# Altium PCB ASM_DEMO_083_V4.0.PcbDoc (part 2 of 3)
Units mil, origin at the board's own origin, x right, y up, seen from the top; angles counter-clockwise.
Board outline 4534.65 x 3225.59 mil, 2 copper layers (Top Layer, Bottom Layer); 192 components, 109 nets, 496 pads, 1295 vias.
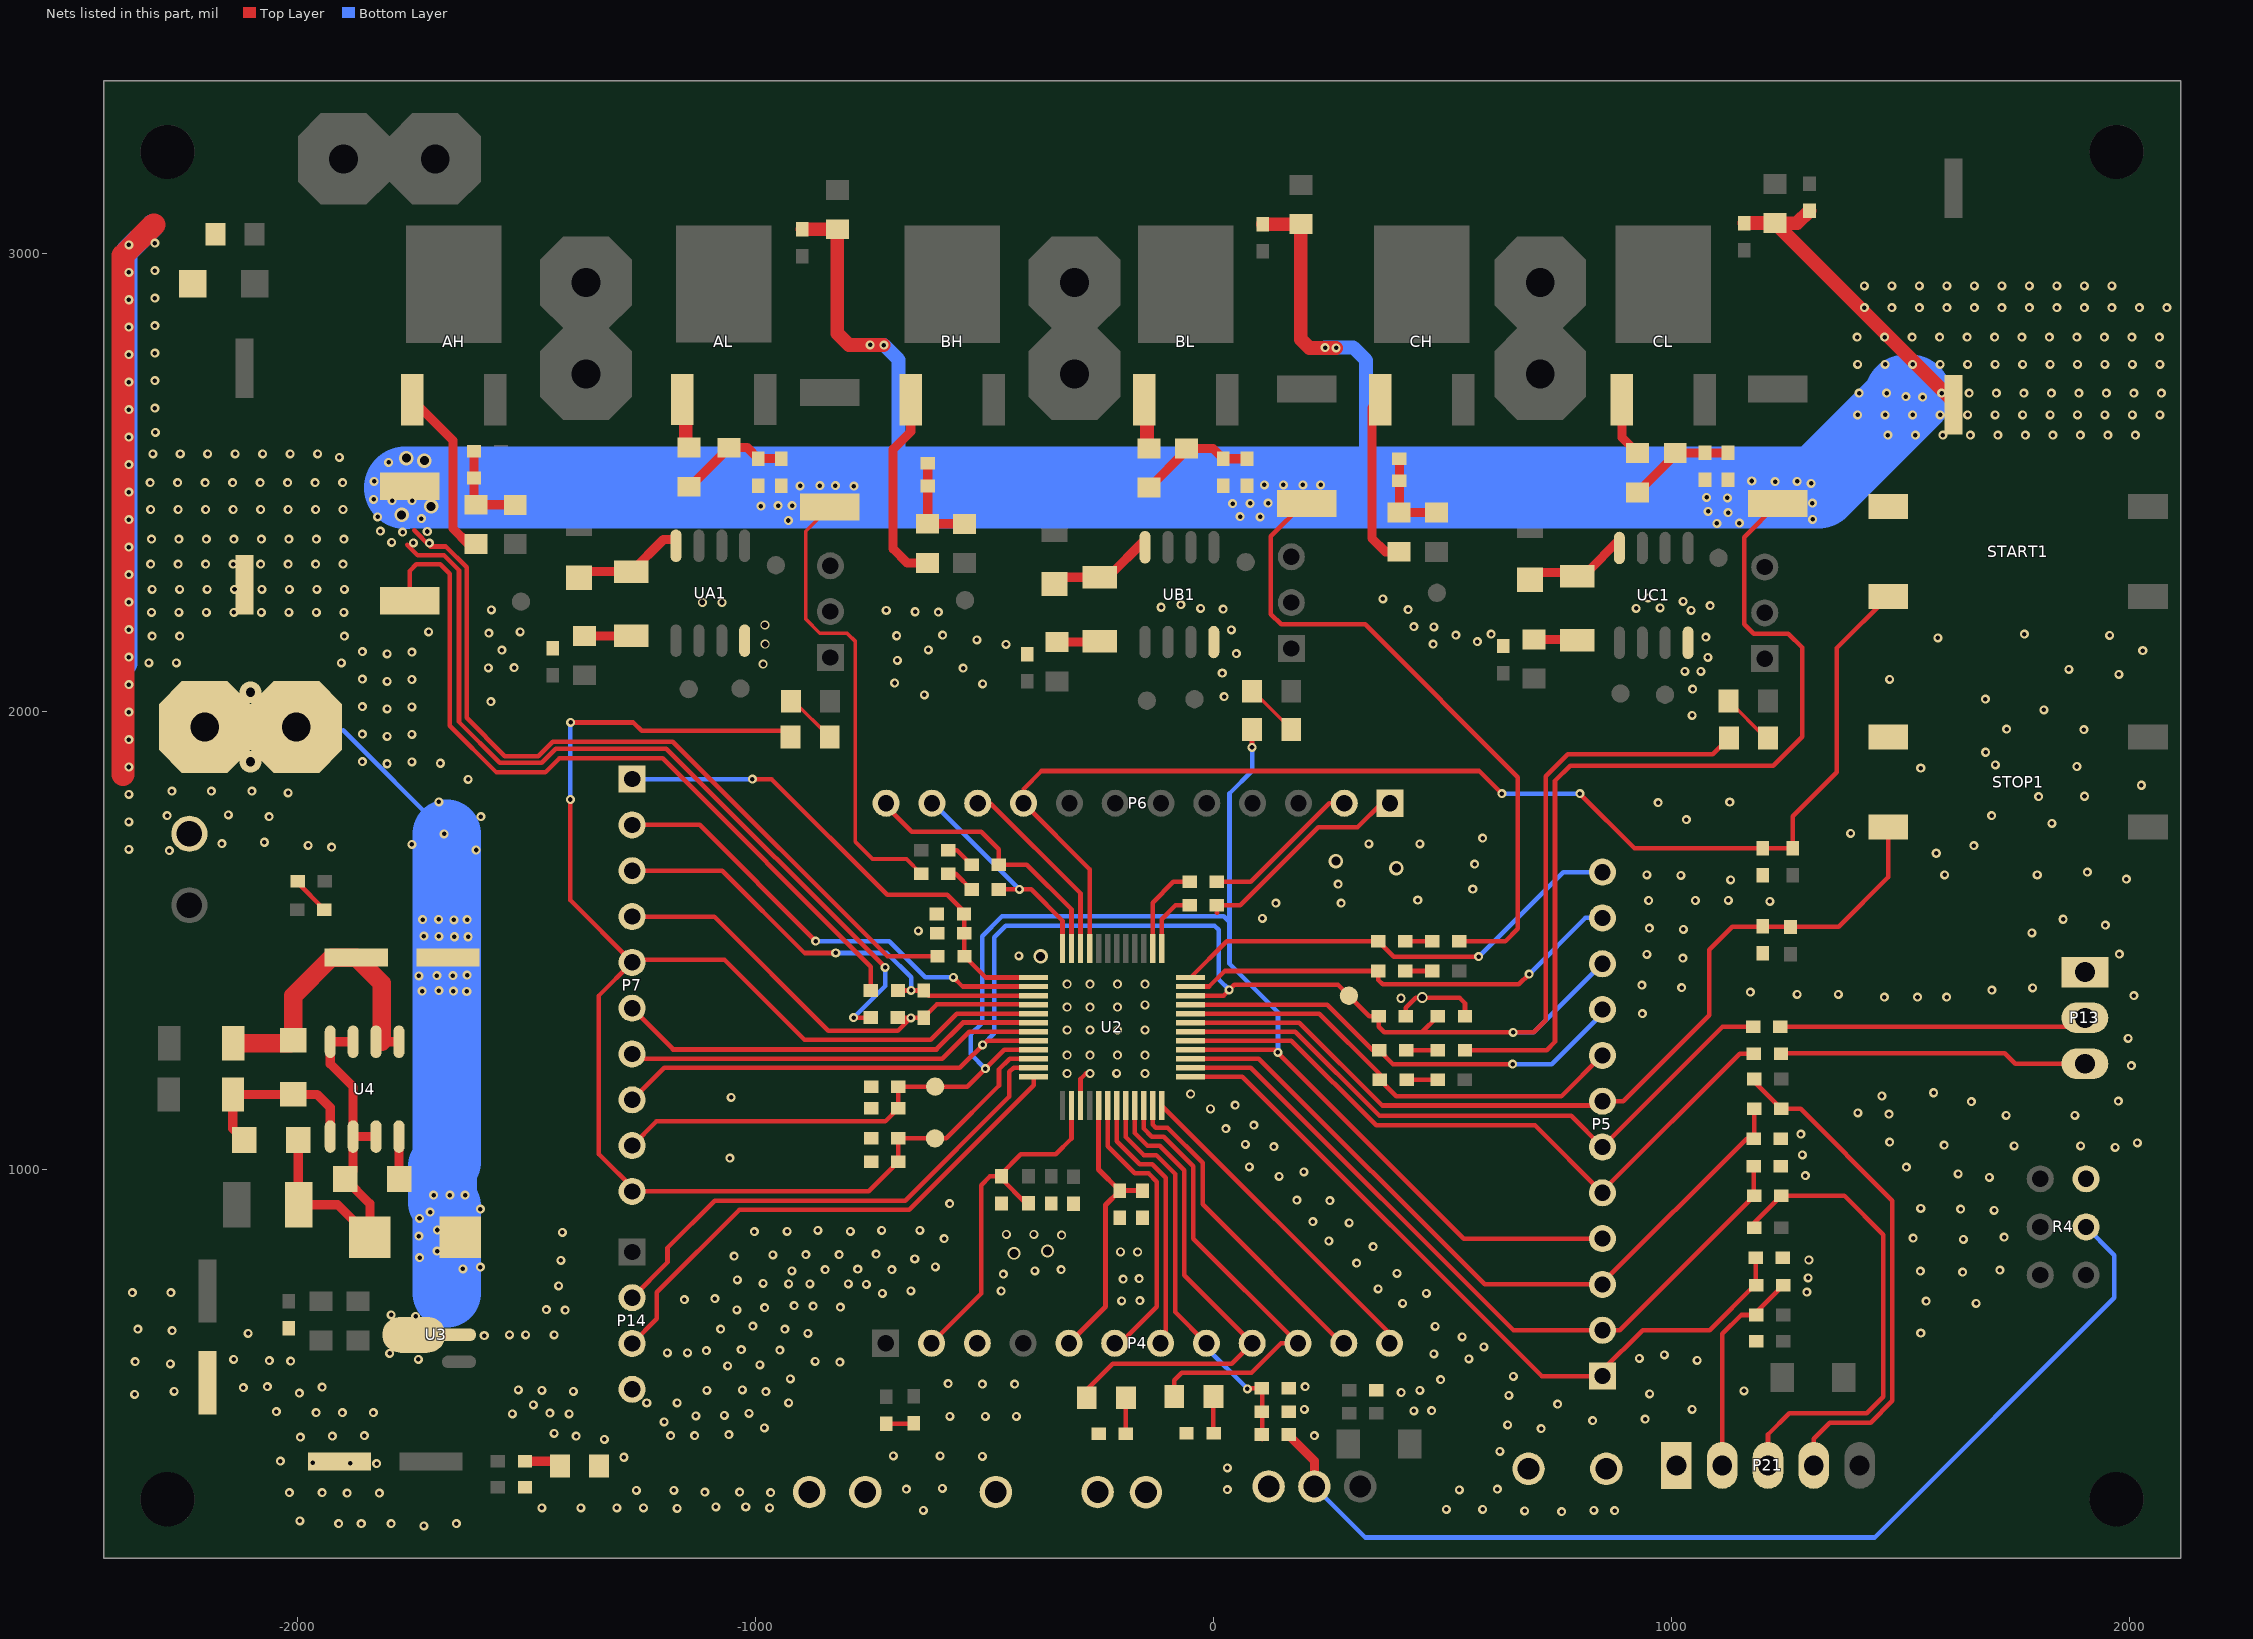
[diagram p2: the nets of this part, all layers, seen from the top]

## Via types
v1: diameter 19.68, hole 9.84, Top Layer to Bottom Layer, 1240 vias
v2: diameter 19.68, hole 11.81, Top Layer to Bottom Layer, 33 vias
v3: diameter 47.24, hole 20, Top Layer to Bottom Layer, 10 vias
v4: diameter 31.5, hole 19.68, Top Layer to Bottom Layer, 7 vias
v5: diameter 27.56, hole 19.68, Top Layer to Bottom Layer, 2 vias
v6: diameter 19.68, hole 13.78, Top Layer to Bottom Layer, 2 vias
v7: diameter 23.62, hole 15.75, Top Layer to Bottom Layer, 1 vias

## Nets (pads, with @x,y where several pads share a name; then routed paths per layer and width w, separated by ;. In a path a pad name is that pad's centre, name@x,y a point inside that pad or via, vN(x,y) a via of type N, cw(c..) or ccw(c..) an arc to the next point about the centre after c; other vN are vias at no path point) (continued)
GND: AGND.1 C1.2 C2.1 C3.2 C6.1 C12.2 C15.1 C17.1 C19.1 C21.2 C23.1 C25.1 C26.1 C27.1 C28.2 C31.2 C32.2 C33.2 C36.2 C37.1 C43.1 C44.1 C45.1 C561.2 C581.2 C601.2 CA-5.1 CC3.2 CF1.2 D02.1 DM_IN.2 G1.1 G2.1 G3.1 G4.1 G5.1 G12.1 G13.1 G14.1 LED.2 P4.3 P13.1 P14.4 P21.1 R4.2 R10.2 R14.2 R20.1 R43.1 R56.2 R58.2 R60.2 R69.2 R76.1 RA-5.2 RT-1.1 START1.1 STOP1.1 U2.3 U3.2 UA1.4 UB1.4 UC1.4 | length 5585.3
  Top Layer w10: R69.2@-1754.72,2242.13 -1754.72,2307.09 -1740.16,2321.65 -1687.8,2321.65 -1666.93,2300.79 -1666.93,1969.29 -1564.96,1867.32 -1458.27,1867.32 -1427.56,1898.03 -1202.36,1898.03 -747.64,1443.31 RT-1.1@-747.64,1391.34 ; R76.1@-714.57,445.89 C44.1@-653.94,445.89 ; U2.3@-290.06,1140.14 -290.06,1198.13 -278.05,1210.14 v2(-269.43,1210.14) ; R60.2@420.08,1335.51 420.08,1354.02 441.73,1375.67 537.32,1375.67 549.21,1363.78 C601.2@549.21,1335.04
  Top Layer w50: -2380.31,1862.6 -2380.31,2995.67 -2312.99,3062.99
  Bottom Layer w10: -1899.61,1959.06 v1@-1673.62,1733.07
  Bottom Layer w50: -2373.23,2105.12 -2373.23,3002.76 -2314.96,3061.02
  Bottom Layer w150: -1673.62,731.1 -1673.62,920.2 -1682.64,929.22 -1682.64,1007.79 -1673.62,1016.8 v1@-1673.62,1733.07
  other v1: -1723.62,222.83 -1909.84,227.56 -1860.24,227.56 -1794.88,227.56 -1652.36,227.56 -1994.09,233.46 760.24,253.54 679.13,255.12 -633.07,256.3 830.32,256.3 875.98,255.91 508.66,258.66 587.8,258.66 -1170.47,260.63 -1466.14,261.81 -1380.71,261.81 -1302.36,261.81 -1244.09,261.81 -968.9,261.81 -1086.22,264.17 -1020.87,264.17 -1890.94,294.09 -1820.87,294.09 -2016.93,295.28 -1945.67,295.28 -966.54,295.28 -1110.24,296.46 -1034.25,296.46 -1259.45,300 -1177.56,300 537.01,301.18 30.71,301.97 -670.08,302.76 619.69,302.76 -591.73,304.72 30.71,349.21 -1826.77,358.27 -1883.86,359.45 -1965.75,360.63 -2037.01,364.17 -1287.01,372.44 -504.33,374.41 -698.82,375.2 -596.46,375.2 625.2,385.04 -1329.53,411.42 -1992.91,416.14 -1923.23,418.5 -1391.34,418.5 -1853.15,419.68 -1184.65,419.68 -1132.68,419.68 220.47,419.68 -1057.87,422.05 -1438.98,424.41 715.35,435.04 -980.31,436.61 642.52,443.31 -1199.21,449.61 827.95,452.36 942.52,455.51 -575.2,461.42 -497.64,461.42 -429.92,461.42 -1129.92,462.99 -1067.72,463.78 -1530.31,467.32 -1406.69,467.32 -1448.43,468.5 -1013.78,468.11 -1958.66,469.68 -1901.57,469.68 -1833.86,469.68 -2045.28,472.05 437.4,473.62 476.38,474.02 198.82,477.17 1045.28,476.77 -1484.65,486.61 751.18,488.19 -1237.01,490.94 -1170.47,490.94 -927.17,490.94 644.88,507.48 -2355.12,509.84 952.36,511.02 -1995.28,512.6 409.84,513.78 -2268.5,516.14 -1397.24,516.14 -977.17,515.75 1158.27,517.32 -1466.14,518.5 -1105.51,518.5 450.79,518.5 -1517.32,519.68 -1028.35,519.68 -2117.72,524.41 -1945.67,525.59 -2065.35,526.77 200.39,526.77 -504.33,532.28 -433.86,532.28 -579.13,533.07 496.06,542.13 -923.23,543.31 654.72,548.82 -1060.24,571.65 -990.16,574.02 -2276.77,576.38 -815.35,579.92 -2353.94,581.1 -2014.57,582.28 -869.29,581.89 -2060.63,583.46 1055.91,583.86 -2138.98,585.83 -1735.43,585.83 557.48,587.4 929.92,588.19 984.25,596.06 481.1,598.03 -1798.43,599.21 -1191.73,600.39 -1148.03,600.39 -1106.69,605.12 -946.46,606.3 -1030.71,607.48 590.55,613.39 542.91,635.43 -1591.73,638.19 -1536.61,639.76 -1501.18,639.76 -1438.98,639.76 -2107.09,642.91 -885.43,642.91 1544.09,643.31 -2273.23,648.82 -2348.03,652.36 -1075.59,652.36 -935.43,652.36 483.86,658.27 -1005.51,658.66 -1741.34,679.92 -1794.88,683.46 -1455.91,694.49 -1414.96,693.7 -1040.16,694.09 -979.53,698.82 -814.57,700 -874.02,702.36 -915.35,703.54 412.99,708.27 1664.96,708.27 1555.91,712.99 -200.39,713.78 -160.63,714.57 -1154.72,716.54 -1088.19,718.5 -722.44,729.92 464.96,730.31 -2359.84,731.89 -2275.59,731.89 1295.67,732.68 -463.39,735.35 -660.63,735.83 359.45,739.76 -1429.53,746.46 -757.48,749.61 -927.17,750.79 -881.1,750.79 -796.85,750.79 -983.07,751.97 -1038.98,759.45 -197.24,761.42 -162.2,762.2 1298.03,763.78 -458.66,772.36 400.79,774.02 1635.43,776.77 -920.08,779.53 -389.76,779.45 1543.31,778.74 1716.93,780.71 -847.64,781.89 -701.97,781.89 -332.68,781.81 -1638.19,783.46 -776.38,783.07 -1600.39,787.4 -607.09,787.8 312.6,796.06 -1424.41,801.97 -651.97,805.51 -1732.68,808.27 -1046.46,811.42 -961.81,814.17 -889.76,814.96 -816.93,814.96 -736.22,815.75 -1694.49,822.44 348.43,832.28 251.97,844.49 1637.4,848.03 -587.8,849.61 1527.56,850.79 1725.98,852.76 -1734.25,855.12 -1421.26,863.39 -1001.97,864.96 -930.71,865.75 -792.52,865.75 -1694.09,868.5 -863.39,867.72 -724.41,867.72 -640.55,867.72 296.46,884.25 216.93,886.61 -1733.07,893.7 -1709.84,907.48 1704.33,911.42 -1600,914.17 1631.1,914.17 1544.09,915.75 -575.98,925.98 254.33,932.68 182.28,933.86 -1702.36,944.49 -1666.54,944.49 -1633.46,944.49 1694.09,983.46 143.31,985.43 1292.13,987.4 1625.59,990.94 197.64,995.28 1512.99,1005.51 78.74,1006.3 -1055.51,1025.59 1285.83,1032.28 1968.5,1048.82 131.89,1050.39 1748.03,1051.97 1893.31,1051.97 1595.28,1053.94 69.69,1055.51 2016.93,1058.66 1476.38,1060.24 1282.28,1077.56 27.17,1089.76 88.19,1097.24 1730.71,1118.9 1880.71,1118.9 1474.8,1121.65 1407.09,1124.41 47.64,1141.34 1654.72,1148.82 1975.59,1150 -1052.76,1157.87 1459.06,1161.02 1572.44,1168.11 -211.42,1210.63 2003.94,1227.56 1996.85,1287.01 936.22,1340.94 1464.57,1376.77 1537.01,1376.77 1600.79,1376.77 2009.45,1380.31 1274.41,1383.07 1364.17,1383.07 1172.05,1387.8 -1629.92,1389.37 -1727.56,1389.76 -1659.06,1390.16 -1690.94,1390.94 1699.61,1392.13 1022.05,1397.64 1788.19,1396.85 935.43,1403.15 -1734.65,1423.23 -1695.28,1424.02 -1660.24,1424.02 -1629.13,1424.8 1024.8,1461.81 -424.8,1466.93 946.46,1470.08 1977.56,1470.87 -1690.94,1509.45 -1657.09,1508.66 -1626.77,1508.66 -1723.62,1510.24 1786.61,1517.32 -644.09,1521.65 1025.98,1524.8 951.57,1527.56 1947.24,1533.86 -1726.38,1546.06 -1691.34,1546.46 -1658.27,1545.67 -1629.13,1546.06 1855.12,1546.85 107.09,1548.82 136.22,1582.28 278.74,1582.28 1214.96,1585.83 446.06,1588.58 950,1587.8 1052.36,1587.8 1124.02,1588.19 566.14,1612.6 272.44,1623.62 1129.13,1632.68 1992.91,1634.25 1020.47,1642.52 946.46,1643.7 1596.46,1643.7 1798.43,1643.7 1907.87,1649.61 570.47,1667.32 1577.95,1690.94 -2279.13,1696.85 -1609.45,1698.03 -2367.32,1699.21 -1924.8,1704.33 1660.24,1707.48 -1975.98,1708.27 -1749.61,1710.24 339.37,1711.42 450.79,1711.42 -2164.57,1712.2 -2071.65,1714.96 587.8,1724.02 -1679.53,1733.07 1390.94,1734.25 1830.32,1755.91 -2367.32,1759.21 1032.28,1764.17 -2061.42,1770.87 -1599.21,1770.87 -2283.86,1772.83 1698.82,1773.23 -2150.39,1774.8 970.87,1801.57 -1690.94,1803.15 1127.17,1802.76 1801.18,1814.57 1901.57,1815.35 -2367.32,1819.21 -2019.68,1822.83 -2273.62,1826.77 -2187.4,1826.77 -2099.21,1826.77 2025.98,1839.37 -1626.77,1852.36 1544.09,1876.77 -2367.32,1879.21 1885.04,1880.31 1707.09,1883.86 -1803.94,1886.3 -1687.4,1887.4 -1749.61,1890.24 -1857.87,1891.02 1685.83,1911.42 -2367.32,1939.21 -1803.94,1946.3 -1749.61,1950.24 -1857.87,1951.02 1900,1960.63 1731.5,1961.81 1045.28,1992.13 -2367.32,1999.21 1812.99,2003.94 -1803.94,2006.3 -1749.61,2010.24 -1857.87,2011.02 -1577.17,2022.05 1685.04,2027.56 23.23,2032.68 -630.71,2036.61 1046.06,2049.21 -2367.32,2059.21 -503.94,2060.63 -696.06,2062.6 -1803.94,2066.3 -1749.61,2070.24 1476.38,2070.47 -1857.87,2071.02 1976.77,2081.5 19.29,2084.25 1029.13,2087.8 1064.17,2087.8 1867.72,2092.52 -546.46,2094.88 -1582.68,2095.67 -1526.77,2096.06 -2323.62,2106.3 -2263.62,2106.3 -1903.62,2106.3 -689.76,2111.81 1079.53,2118.5 -2367.32,2119.21 -1803.94,2126.3 50.39,2126.77 -1749.61,2130.24 -1857.87,2131.02 2028.74,2133.46 -1553.15,2134.25 -622.44,2134.65 -452.76,2146.85 479.53,2147.24 575.98,2153.15 -516.54,2156.69 1581.5,2161.02 1074.8,2162.99 -2316.93,2164.96 -2256.93,2164.96 -1896.93,2164.96 -691.34,2165.75 1956.3,2166.54 -590.94,2167.32 529.53,2167.32 606.3,2169.29 1770.08,2169.29 -1581.5,2171.65 -1712.99,2174.02 -1513.39,2174.02 -2367.32,2179.21 38.98,2178.74 481.5,2185.04 437.4,2185.83 -2318.11,2216.93 -2258.11,2216.93 -2198.11,2216.93 -2138.11,2216.93 -2078.11,2216.93 -2018.11,2216.93 -1958.11,2216.93 -1898.11,2216.93 -600.39,2217.32 -651.18,2218.11 -714.17,2221.26 1042.91,2221.26 -1576.38,2222.05 21.26,2223.62 424.8,2222.83 -27.95,2225.59 922.83,2225.59 975.2,2226.38 -114.17,2227.95 1084.25,2231.5 -71.26,2233.46 -2367.32,2239.21 1025.59,2240.94 370.08,2246.06 949.21,2248.43 -2316.93,2266.93 -2256.93,2266.93 -2196.93,2266.93 -2136.93,2266.93 -2076.93,2266.93 -2016.93,2266.93 -1956.93,2266.93 -1896.93,2266.93 -2367.32,2299.21 -2320.08,2322.05 -2260.08,2322.05 -2200.08,2322.05 -2140.08,2322.05 -2080.08,2322.05 -2020.08,2322.05 -1960.08,2322.05 -1900.08,2322.05 -2367.32,2359.21 -2318.11,2376.77 -2258.11,2376.77 -2198.11,2376.77 -2138.11,2376.77 -2078.11,2376.77 -2018.11,2376.77 -1958.11,2376.77 -1898.11,2376.77 -2367.32,2419.21 -2320.08,2441.34 -2260.08,2441.34 -2200.08,2441.34 -2140.08,2441.34 -2080.08,2441.34 -2020.08,2441.34 -1960.08,2441.34 -1900.08,2441.34 -2367.32,2479.21 -2320.87,2500 -2260.87,2500 -2200.87,2500 -2140.87,2500 -2080.87,2500 -2020.87,2500 -1960.87,2500 -1900.87,2500 -2367.32,2539.21 -1907.87,2555.12 -2315.35,2562.6 -2255.35,2562.6 -2195.35,2562.6 -2135.35,2562.6 -2075.35,2562.6 -2015.35,2562.6 -1955.35,2562.6 -2367.32,2599.21 -2309.84,2609.45 -2367.32,2659.21 -2310.63,2662.68 -2367.32,2719.21 -2310.63,2722.68 -2367.32,2779.21 -2310.63,2782.68 -2367.32,2839.21 -2310.63,2842.68 -2367.32,2899.21 -2310.63,2902.68 -2367.32,2959.21 -2310.63,2962.68 -2367.32,3019.21 -2310.63,3022.68
  other v2: 1299.76,803.03 -165.35,820.47 -202.76,820.87 -331.1,857.48 -451.97,859.06 -392.13,859.06 -6.3,1133.07 -49.61,1165.35 -319.43,1210.14 -149.43,1210.14 -319.43,1250.14 -269.43,1250.14 -209.43,1250.14 -149.43,1250.14 -319.43,1305.14 -269.43,1305.14 -209.43,1305.14 -149.43,1305.14 -319.43,1355.14 -269.43,1355.14 -209.43,1355.14 -149.43,1360.14 409.45,1374.41 -319.43,1405.14 -269.43,1405.14 -209.43,1405.14 -149.43,1405.14 -983.07,2103.54 -1115.72,2238.68 -1072.72,2238.68
  other v3: -2101.97,1890.54 -2101.97,2042.54
  other v4: -377.17,1465.75 399.21,1658.27 267.32,1673.62
  other v5: -435.43,817.64 -362.2,822.76
  other v6: -978.35,2147.24 -979.13,2189.37
  other v7: 455.91,1375.98
HALL_A: C31.1 P5.3 R54.2 U2.15 | length 1632.3
  Top Layer w10: U2.15@-49.9,1242.5 99.23,1242.5 592.05,749.68 P5.3@849.21,749.68 849.21,753.26 1163.98,1068.03 C31.1@1179.76,1068.03 ; C31.1@1180.24,1068.5 R54.2@1180.24,1133.03
HALL_B: C32.1 P5.2 R57.2 U2.14 | length 1653.6
  Top Layer w10: U2.14@-49.9,1222.82 81.91,1222.82 655.04,649.68 P5.2@849.21,649.68 886.89,649.68 R57.2@1180.24,943.03 ; R57.2@1179.76,943.5 C32.1@1179.76,1008.03
HALL_C: C33.1 P5.1 R62.2 U2.13 | length 1652.4
  Top Layer w10: U2.13@-49.9,1203.13 63.01,1203.13 716.46,549.68 P5.1@849.21,549.68 849.21,562.05 936.85,649.68 1083.35,649.68 1183.46,749.8 C33.1@1183.46,808.03
LDO15: C27.2 C28.1 P4.5 U2.5 | length 633.7
  Top Layer w11: P4.5@-315.35,621.26 -235.43,701.18 -235.43,923.23 C27.2@-204.33,954.33 ; U2.5@-250.69,1140.14 -250.69,1000.69 C27.2@-204.33,954.33 ; C28.1@-154.72,954.33 C27.2@-204.33,954.33
LED2: L2.1 P4.9 U2.9 | length 1061.8
  Top Layer w10: L2.1@-276.61,502.34 -276.61,519.8 -219.68,576.73 40.12,576.73 P4.9@84.65,621.26 -63.62,769.53 -63.62,999.03 -116.71,1052.13 -143.86,1052.13 -171.95,1080.21 U2.9@-171.95,1140.14
LED3: L1.1 P4.10 U2.10 | length 1012.7
  Top Layer w10: U2.10@-152.26,1140.14 -152.26,1090.05 -134.33,1072.13 -108.43,1072.13 -43.62,1007.32 -43.62,849.53 P4.10@184.65,621.26 147.62,621.26 83.09,556.73 -69.29,556.73 -85.63,540.39 L1.1@-85.63,505.12
LKS_PIN10: P4.7 U2.7 | length 584.6
  Top Layer w10: U2.7@-211.32,1140.14 -211.32,1062.5 -160.94,1012.13 -133.28,1012.13 -103.62,982.47 -103.62,632.99 P4.7@-115.35,621.26
LKS_PIN11: P4.6 U2.6 | length 626.2
  Top Layer w10: U2.6@-231,1140.14 -231,1051.47 -171.65,992.13 -141.57,992.13 -123.62,974.18 -123.62,700.69 -203.06,621.26 P4.6@-215.35,621.26
NetAH_1: AH.1 K1.2 | length 382.5
  Top Layer w20: AH.1@-1749.21,2681.1 -1660.24,2592.13 -1660.24,2400 -1626.18,2365.94 K1.2@-1609.84,2365.94
NetAL_1: AL.1 K2.2 | length 112.7
  Top Layer w20: AL.1@-1164.57,2681.1 AL.1@-1151.97,2668.5
  Top Layer w30: AL.1@-1151.97,2668.5 -1151.97,2583.66 K2.2@-1144.88,2576.57
NetBH_1: BH.1 K3.2 | length 429.6
  Top Layer w20: BH.1@-660.63,2681.1 -660.63,2611.42 -699.21,2572.83 -699.21,2355.51 -668.31,2324.61 K3.2@-624.02,2324.61
NetBL_1: BL.1 K4.2 | length 67.8
  Top Layer w30: K4.2@-144.88,2573.97 BL.1@-144.88,2641.73
NetC7_1: C7.1 K1.1 K+A1.2 R21.2 | length 204.2
  Top Layer w20: C7.1@-1614.12,2510.11 R21.2@-1614.17,2568.11 ; C7.1@-1614.12,2510.11 -1614.12,2455.85 K1.1@-1609.84,2451.57 -1524.21,2451.57 K+A1.2@-1524.02,2451.38
NetC11_1: C11.1 K2.1 K-A1.1 R31.2 | length 246.9
  Top Layer w20: K2.1@-1144.88,2490.94 -1142.52,2490.94 K-A1.1@-1057.48,2575.98 ; K-A1.1@-1057.48,2576.77 -1017.61,2576.77 R31.2@-993.28,2552.44 -993.2,2552.36 C11.1@-943.31,2552.36
NetC16_1: C16.1 K3.1 K+B1.2 R39.2 | length 212.8
  Top Layer w20: R39.2@-623.62,2542.13 -623.62,2410.63 K3.1@-624.02,2410.24 -543.5,2410.24 K+B1.2@-543.31,2410.04
NetC20_1: C20.1 K4.1 K-B1.1 R45.2 | length 261.3
  Top Layer w20: K4.1@-140.45,2489.02 -58.66,2570.81 K-B1.1@-58.66,2574.8 -1.18,2574.8 R45.2@21.65,2551.97 73.28,2551.97 C20.1@73.44,2551.81
NetC24_1: C24.1 K5.1 K+C1.2 R50.2 | length 200
  Top Layer w20: R50.2@405.91,2551.97 405.91,2435.43 K5.1@405.12,2434.65 405.32,2434.45 K+C1.2@487.4,2434.45
NetC34_1: C34.1 K6.1 K-C1.1 R63.2 | length 232.8
  Top Layer w20: K6.1@926.18,2478.7 1012.5,2565.02 C34.1@1123.25,2565.02
NetCAH1_1: CAH1.1 D1.2 UA1.8 | length 240.8
  Top Layer w20: CAH1.1@-1385.04,2305.91 -1271.44,2305.91 D1.2@-1270.91,2305.37 -1200.38,2375.9 UA1.8@-1173.69,2375.9
NetCBH1_1: CBH1.1 D2.2 UB1.8 | length 230.6
  Top Layer w20: CBH1.1@-346.06,2293.31 -230.62,2293.31 UB1.8@-149.21,2374.72
NetCCH1_1: CCH1.1 D4.2 UC1.8 | length 225.3
  Top Layer w20: CCH1.1@690.55,2303.54 814.65,2303.54 UC1.8@886.22,2375.11
NetCF1_1: CF1.1 DD6.2 RP1.2 U4.5 U4.6 | length 659
  Top Layer w20: U4.6@-1827.95,1279.44 -1815.75,1279.44 U4.5@-1777.95,1279.44
  Top Layer w40: DD6.2@-2139.44,1275.84 -2015.5,1275.84 RP1.2@-2008.66,1282.68 -2008.66,1379.53 -1925.2,1462.99 CF1.1@-1871.26,1462.99 -1815.75,1407.48 -1815.75,1279.44
NetCF2_1: CF2.1 DP1.2 RP1.1 U4.1 | length 418.7
  Top Layer w20: DP1.2@-2140.23,1164.42 -2008.81,1164.42 RP1.1@-2008.66,1164.57 -1956.69,1164.57 -1927.95,1135.83 U4.1@-1927.95,1072.44 ; DP1.2@-2139.2,1182.28 -2140.62,1183.71 -2140.62,1089.83 CF2.1@-2115.75,1064.96
NetCF2_2: CF2.2 D02.2 PL1.2 RP2.2 U4.2 U4.3 U4.7 U4.8 | length 902.8
  Top Layer w20: CF2.2@-1997.64,1064.96 -1997.64,924.37 PL1.2@-1996.89,923.62 -1911.89,923.62 D02.2@-1841.41,853.15 -1841.41,926.06 RP2.2@-1895.28,979.92 -1877.95,997.24 U4.2@-1877.95,1072.44 ; U4.7@-1877.95,1279.44 U4.8@-1927.95,1279.44 -1927.95,1231.1 -1877.95,1181.1 U4.2@-1877.95,1072.44 ; U4.3@-1827.95,1072.44 U4.2@-1877.95,1072.44
NetCH_1: CH.1 K5.2 | length 381.2
  Top Layer w20: CH.1@364.17,2681.1 346.06,2662.99 346.06,2378.74 375.79,2349.02 K5.2@405.12,2349.02
NetCL_1: CL.1 K6.2 | length 131
  Top Layer w20: CL.1@891.73,2681.1 891.73,2598.78 K6.2@926.18,2564.33
NetD1_1: D1.1 R79.2 | length 102
  Top Layer w20: R79.2@-1372.83,2165.16 -1271.12,2165.16 D1.1@-1270.91,2165.37
NetD2_1: D2.1 R78.2 | length 94.2
  Top Layer w20: R78.2@-341.34,2151.77 -249.74,2151.77 D2.1@-247.88,2153.63
NetD4_1: D4.1 R77.2 | length 96.7
  Top Layer w20: R77.2@700,2157.68 D4.1@796.49,2157.68 ; D4.1@796.89,2169.88 D4.1@797,2169.77
NetL1_2: L1.2 R14.1 | length 80.3
  Top Layer w10: R14.1@0,424.81 L1.2@0,505.12
NetL2_2: L2.2 R10.1 | length 78.3
  Top Layer w10: L2.2@-190.98,502.34 -190.98,424.06 R10.1@-190.94,424.02
NetLED_1: LED.1 R65.2 | length 80.4
  Top Layer w20: R65.2@-1502.76,363.78 -1436.88,363.78 LED.1@-1426.61,353.51
NetP13_2: P13.2 R12.1 | length 672.7
  Top Layer w10: R12.1@1237.8,1311.81 1882.68,1311.81 P13.2@1902.36,1331.5
NetP13_3: P13.3 R9.2 | length 671.7
  Top Layer w10: R9.2@1238.98,1254.33 1727.17,1254.33 1750,1231.5 P13.3@1901.18,1231.5
NetP21_2: P21.2 R51.1 R62.1 | length 468.2
  Top Layer w10: P21.2@1110.63,354.72 1110.63,641.73 1151.93,683.03 R51.1@1185.24,683.03 1185.24,688.98 R62.1@1244.29,748.03
NetP21_3: P21.3 R52.1 R57.1 | length 1060
  Top Layer w10: R52.1@1180.24,873.03 1180.24,883.98 R57.1@1239.29,943.03 1377.56,943.03 1462.6,857.99 1462.6,504.33 1426.38,468.11 1256.69,468.11 1210.63,422.05 P21.3@1210.63,354.72
NetP21_4: P21.4 R53.1 R54.1 | length 1116.6
  Top Layer w10: R53.1@1180.24,1198.03 1180.24,1192.09 R54.1@1239.29,1133.03 1281.93,1133.03 1482.28,932.68 1482.28,495.73 1434.66,448.11 1345.67,448.11 1310.63,413.07 P21.4@1310.63,354.72
NetR1_1: R1.1 R55.2 | length 117.3
  Top Layer w8: R1.1@-922.44,2022.83 -915.94,2022.83 R55.2@-837.6,1944.49
NetR2_1: R2.1 R59.2 | length 120
  Top Layer w8: R2.1@84.25,2044.49 86.81,2044.49 R59.2@169.88,1961.42
NetR3_1: R3.1 R61.2 | length 119.8
  Top Layer w8: R3.1@1124.8,2023.62 1206.3,1942.13 R61.2@1210.83,1942.13
NetR8_1: R8.1 U2.25 | length 137.7
  Top Layer w10: U2.25@-112.89,1482.66 -112.89,1546.95 -82.68,1577.17 R8.1@-51.97,1577.17
NetR11_2: R11.2 U2.26 | length 199.8
  Top Layer w10: U2.26@-132.57,1482.66 -132.57,1583.17 -87.4,1628.35 R11.2@-51.97,1628.35
NetR74_2: R74.2 R75.1 | length 86.5
  Top Layer w10: R75.1@-1999.21,1629.92 -1999.21,1626.38 R74.2@-1940.55,1567.72
NetRP2_1: RP2.1 U4.4 | length 92.8
  Top Layer w20: U4.4@-1777.95,1072.44 -1777.95,980.71 RP2.1@-1777.17,979.92
NetRPA1_1: RPA1.1 RPA2.2 | length 64.4
  Top Layer w10: RPA2.2@-579.13,1697.64 -559.84,1697.64 RPA1.1@-527.95,1665.75
NetRPA3_1: RPA3.1 RPA4.2 | length 65
  Top Layer w10: RPA4.2@-578.74,1646.06 -562.2,1646.06 RPA3.1@-527.95,1611.81
NetRPB1_1: RPB1.1 RPB2.2 | length 59.1
  Top Layer w10: RPB1.1@418.9,1433.94 RPB2.2@477.95,1433.94
NetRPB3_1: RPB3.1 RPB4.2 | length 59.1
  Top Layer w10: RPB3.1@418.9,1498.9 RPB4.2@477.95,1498.9
NetRPC1_1: RPC1.1 RPC2.2 | length 67.5
  Top Layer w10: RPC1.1@422.05,1196.46 488.98,1196.46 RPC2.2@489.37,1196.85
NetRPC3_1: RPC3.1 RPC4.2 | length 69.3
  Top Layer w10: RPC3.1@420.87,1261.02 RPC4.2@490.16,1261.02
NRST: C21.1 P4.2 R48.1 U2.2 | length 791.5
  Top Layer w10: P4.2@-615.35,621.26 -506.69,729.92 -506.69,966.54 -487.8,985.43 C21.1@-462.6,985.43 ; R48.1@-403.54,926.77 -409.37,926.77 -462.6,980 C21.1@-462.6,985.43 ; U2.2@-309.74,1140.14 -309.74,1068.21 -344.09,1033.86 -420.39,1033.86 -462.6,991.65 C21.1@-462.6,985.43
OC: C17.2 P7.1 R20.2 R38.1 U2.37 | length 1101
  Top Layer w10: v1(-1006.3,1852.76) -964.57,1852.76 -711.81,1600 -580.71,1600 R20.2@-544.88,1564.17 ; R20.2@-544.09,1553.15 C17.2@-544.09,1516.54 -544.09,1466.93 R38.1@-543.31,1466.14 -496.83,1419.67 U2.37@-392.42,1419.67
  Bottom Layer w10: P7.1@-1268.9,1852.76 v1(-1006.3,1852.76)
OPA1_IN: P5.9 RPC3.2 U2.21 | length 993.5
  Top Layer w10: U2.21@-49.9,1360.62 248.43,1360.62 RPC3.2@348.02,1261.02 ; RPC3.2@361.81,1261.02 392.13,1230.71 v1(653.15,1230.71)
  Bottom Layer w10: v1(653.15,1230.71) 738.98,1230.71 849.21,1340.94 P5.9@849.21,1349.68
OPA1_IP: P5.8 RPC1.2 U2.20 | length 1018.4
  Top Layer w10: U2.20@-49.9,1340.93 231.12,1340.93 362.99,1209.06 RPC1.2@362.99,1196.46 399.21,1160.24 759.76,1160.24 P5.8@849.21,1249.68
OPA2_IN: P5.12 RPB3.2 U2.24 | length 1022.2
  Top Layer w10: U2.24@-49.9,1419.67 29.33,1498.9 RPB3.2@359.84,1498.9 393.39,1465.35 v1(579.13,1465.35)
  Bottom Layer w10: v1(579.13,1465.35) 763.46,1649.68 P5.12@849.21,1649.68
OPA2_IP: P5.11 RPB1.2 U2.23 | length 1003.6
  Top Layer w10: U2.23@-49.9,1399.99 -9.58,1399.99 24.37,1433.94 RPB1.2@359.84,1433.94 ; RPB1.2@366.54,1433.94 RPB1.2@359.84,1433.94 ; v1(689.37,1427.17) 666.93,1404.72 369.29,1404.72 359.84,1414.17 RPB1.2@359.84,1433.94
  Bottom Layer w10: v1(689.37,1427.17) 811.89,1549.68 P5.11@849.21,1549.68
OPA3_IN: P6.11 RPA3.2 U2.36 | length 497.5
  Top Layer w10: RPA3.2@-468.9,1612.2 v1(-423.62,1612.2) -398.03,1612.2 -329.42,1543.6 U2.36@-329.42,1482.66
  Bottom Layer w10: P6.11@-614.43,1800.14 -611.56,1800.14 v1(-423.62,1612.2)
OPA3_IP: P6.12 RPA1.2 U2.35 | length 609.5
  Top Layer w10: P6.12@-714.43,1800.14 -714.43,1793.95 -658.27,1737.8 -506.69,1737.8 -468.9,1700 -468.9,1666.14 -407.87,1666.14 ; -407.48,1666.14 -309.74,1568.4 U2.35@-309.74,1482.66
OPA4_IN: CT1.2 P7.3 RT-1.2 U2.39 | length 1034.6
  Top Layer w10: P7.3@-1268.9,1652.76 -1072.05,1652.76 -892.52,1473.23 v1(-824.41,1473.23) ; RT-1.2@-688.58,1391.34 CT1.2@-632.68,1391.34 -621.64,1380.3 U2.39@-392.42,1380.3
  Bottom Layer w10: v1(-824.41,1473.23) -712.9,1473.23 -659.84,1420.17 v1(-659.84,1391.73)
OPA4_IP: CT1.1 P7.4 RT+1.2 U2.40 | length 1039.8
  Top Layer w10: P7.4@-1268.9,1552.76 -1089.76,1552.76 -840.51,1303.5 -688.62,1303.5 v1(-660.63,1331.5) ; RT+1.2@-697.24,1331.5 v1(-660.63,1331.5) ; U2.40@-392.68,1360.87 -604.09,1360.87 CT1.1@-632.68,1332.28 -633.46,1331.5 v1(-660.63,1331.5)
P2.11: P4.11 U2.11 | length 709.8
  Top Layer w10: U2.11@-132.58,1140.14 -132.58,1098.72 -125.98,1092.13 -100.15,1092.13 -23.62,1015.6 -23.62,924.41 279.53,621.26 P4.11@284.65,621.26
P2.12: P4.12 U2.12 | length 725
  Top Layer w10: U2.12@-112.89,1140.14 384.65,642.61 P4.12@384.65,621.26
PA: C561.1 P7.5 P7.10 R55.1 R56.1 T1.1 U2.41 U2.46 | length 3661.7
  Top Layer w10: v1(-1403.54,1808.27) -1403.54,1588.19 P7.5@-1268.5,1453.15 ; v1(-1403.15,1976.38) -1266.14,1976.38 -1247.87,1958.11 -936.85,1958.11 R55.1@-923.23,1944.49 ; P7.10@-1268.9,952.76 P7.10@-1259.98,952.76 ; P7.10@-1257.35,950.13 P7.10@-1259.98,952.76 ; U2.46@-392.42,1242.5 -444.9,1242.5 -468.11,1219.29 -468.11,1183.86 -583.46,1068.5 T1.1@-607.87,1068.5 R56.1@-687.8,1068.5 C561.1@-687.8,1017.72 -752.76,952.76 P7.10@-1259.98,952.76 ; U2.41@-392.42,1340.93 -559.86,1340.93 -617.28,1283.5 -892.56,1283.5 -1067.32,1458.27 -1263.39,1458.27 P7.5@-1268.9,1452.76 -1341.34,1380.31 -1341.34,1034.12 P7.10@-1259.98,952.76
  Bottom Layer w10: v1(-1403.54,1808.27) v1@-1403.54,1976.38
PB: C581.1 P5.4 P7.9 R58.1 R59.1 T2.1 U2.16 U2.45 | length 3712.2
  Top Layer w10: P7.9@-1268.9,1052.76 -1216.18,1105.47 -716.57,1105.47 C581.1@-687.8,1134.25 ; C581.1@-687.8,1130.32 C581.1@-687.8,1134.25 ; U2.45@-392.42,1262.19 -456.32,1262.19 -537.01,1181.5 R58.1@-687.8,1181.5 C581.1@-687.8,1134.25 ; U2.16@-49.9,1262.19 134.27,1262.19 546.77,849.68 P5.4@849.21,849.68 ; v1(84.25,1922.05) R59.1@84.25,1961.42
  Bottom Layer w10: v1(-497.64,1220.87) -529.53,1252.76 -529.53,1295.67 -504.72,1320.47 -504.72,1509.78 -461.43,1553.07 22.58,1553.07 35.1,1540.55 ; v1@85.04,1924.41 85.04,1871.32 35.1,1821.39 35.1,1540.55 ; v1(140.94,1256.3) 140.94,1343.7 35.1,1449.54 35.1,1540.55
PC: C601.1 P5.10 P7.8 R60.1 R61.1 T3.1 U2.22 U2.44 | length 3946.5
  Top Layer w10: P7.8@-1268.9,1152.76 -1199.15,1222.5 -553.48,1222.5 -494.11,1281.87 U2.44@-392.42,1281.87 ; U2.22@-49.9,1380.3 22.43,1380.3 45.67,1403.54 272.05,1403.54 T3.1@295.67,1379.92 340.08,1335.51 R60.1@361.02,1335.51 361.02,1312.2 373.23,1300 455.12,1300 ; C601.1@490.16,1335.04 455.12,1300 ; R61.1@1125.2,1942.13 1090.16,1907.09 773.62,1907.09 725.67,1859.13 725.67,1326.06 699.61,1300 v1(654.33,1300) 455.12,1300
  Bottom Layer w10: v1(-503.94,1272.44) -478.35,1298.03 -478.35,1507.87 -453.15,1533.07 2.36,1533.07 11.81,1523.62 11.81,1415.35 v1(34.25,1392.91) ; v1(654.33,1300) 699.53,1300 P5.10@849.21,1449.68
PGND: C11.2 C20.2 C34.2 CA.1 CB.1 CC1.2 CC.1 R15.2 R16.1 R17.2 R31.1 R38.2 R45.1 R49.2 R63.1 R69.1 RA1.1 RB1.1 RC1.1 RPA4.1 RPB4.1 RPC4.1 RT+1.1 | length 13704.4
  Top Layer w8: R15.2@-837.8,2446.46 -890.16,2394.1 -890.16,2202.36 -859.06,2171.26 -799.61,2171.26 -781.5,2153.15 -781.5,1715.75 -744.09,1678.35 -670.08,1678.35 RPA4.1@-637.8,1646.06
  Top Layer w10: -1760.24,2364.57 -1737.32,2341.65 -1679.51,2341.65 -1646.93,2309.07 -1646.93,1977.58 -1558.09,1888.74 -1466.38,1888.74 -1435.83,1919.29 -1194.09,1919.29 v1(-716.54,1441.73) ; -1744.88,2395.67 -1709.84,2360.63 -1675.59,2360.63 -1630.21,2315.25 -1630.21,1986.51 -1546.75,1903.05 -1473.84,1903.05 -1442.24,1934.65 -1179.92,1934.65 -711.42,1466.14 R38.2@-602.36,1466.14 ; v1(-785.43,1332.28) RT+1.1@-748.03,1332.28 ; R16.1@203.54,2454.33 197.24,2454.33 125.55,2382.64 125.55,2213.03 148.03,2190.55 331.1,2190.55 664.57,1857.09 664.57,1525.92 637.54,1498.9 RPB4.1@537.01,1498.9 ; RPC4.1@549.21,1261.02 727.62,1261.02 745.67,1279.07 745.67,1848.9 778.82,1882.05 1221.81,1882.05 1285.12,1945.35 1285.12,2140.14 1254.79,2170.47 1179.13,2170.47 1159.02,2190.59 1159.02,2381.06 R17.2@1232.28,2454.33
  Top Layer w30: RA1.1@-897.24,3053.15 CA.1@-820.87,3053.15 -820.87,2825.59 -795.67,2800.39 v1(-719.41,2800.39) ; RB1.1@107.93,3064.25 CB.1@190.93,3064.25 190.93,2812.61 209.46,2794.08 v1(267.72,2794.08) ; RC1.1@1159.06,3066.54 1226.07,3066.54 CC.1@1226.17,3066.43 ; R49.2@1301.18,3093.31 1274.31,3066.43 CC.1@1226.17,3066.43 ; CC1.2@1615.75,2669.69 1615.75,2676.86 CC.1@1226.17,3066.43
  Bottom Layer w10: v1(-785.43,1332.28) -716.54,1401.18 v1(-716.54,1441.73)
  Bottom Layer w30: -764.17,2489.4 -687.4,2566.17 -687.4,2768.39 v1(-719.41,2800.39) -719.8,2800.79 v1(-749.21,2800.79) ; v1(243.7,2794.88) 305.51,2794.88 333.07,2767.32 333.07,2540.19 282.28,2489.4
  Bottom Layer w180: -1764.55,2488.99 -1741.32,2489.4 -764.17,2489.4 282.28,2489.4 1320.11,2489.4 1520.87,2690.16 v1@1511.81,2690.16
  other v1: -1746.46,2368.5 -1711.42,2368.11 -1793.7,2369.68 -1770.08,2392.13 -1716.14,2393.31 -1818.5,2394.09 1098.82,2411.02 1148.43,2411.81 -927.95,2417.32 1308.27,2419.68 -1729.13,2421.26 -1824.41,2425.2 101.97,2425.2 58.27,2425.98 1123.62,2434.65 1079.92,2437.4 -987.8,2448.82 -950,2450 -919.68,2450 42.13,2454.33 79.92,2454.72 119.29,2455.12 1307.48,2455.51 -1792.91,2460.63 -1749.21,2460.63 -1833.46,2463.39 1122.05,2466.93 1076.77,2467.72 -785.04,2492.13 -901.97,2492.91 -859.06,2493.31 -825.2,2493.31 111.42,2494.88 152.76,2495.28 195.28,2494.88 233.86,2495.28 1304.72,2498.43 1225.98,2501.97 -1832.28,2502.76 1175.2,2503.54 1274.41,2502.76 -1800.39,2544.09 1472.44,2603.54 1532.44,2603.54 1592.44,2603.54 1652.44,2603.54 1712.44,2603.54 1772.44,2603.54 1832.44,2603.54 1892.44,2603.54 1952.44,2603.54 2012.44,2603.54 1406.3,2647.64 1466.3,2647.64 1526.3,2647.64 1586.3,2647.64 1646.3,2647.64 1706.3,2647.64 1766.3,2647.64 1826.3,2647.64 1886.3,2647.64 1946.3,2647.64 2006.3,2647.64 2066.3,2647.64 1548.43,2686.61 1511.81,2687.8 1409.45,2695.28 1469.45,2695.28 1589.45,2695.28 1649.45,2695.28 1709.45,2695.28 1769.45,2695.28 1829.45,2695.28 1889.45,2695.28 1949.45,2695.28 2009.45,2695.28 2069.45,2695.28 1406.3,2758.27 1466.3,2758.27 1526.3,2758.27 1586.3,2758.27 1646.3,2758.27 1706.3,2758.27 1766.3,2758.27 1826.3,2758.27 1886.3,2758.27 1946.3,2758.27 2006.3,2758.27 2066.3,2758.27 1405.12,2817.72 1465.12,2817.72 1525.12,2817.72 1585.12,2817.72 1645.12,2817.72 1705.12,2817.72 1765.12,2817.72 1825.12,2817.72 1885.12,2817.72 1945.12,2817.72 2005.12,2817.72 2065.12,2817.72 1421.26,2882.28 1481.26,2882.28 1541.26,2882.28 1601.26,2882.28 1661.26,2882.28 1721.26,2882.28 1781.26,2882.28 1841.26,2882.28 1901.26,2882.28 1961.26,2882.28 2021.26,2882.28 2081.26,2882.28 1421.26,2929.53 1481.26,2929.53 1541.26,2929.53 1601.26,2929.53 1661.26,2929.53 1721.26,2929.53 1781.26,2929.53 1841.26,2929.53 1901.26,2929.53 1961.26,2929.53
  other v4: -1772.03,2429.46 -1707.86,2448.36 -1722.43,2547.97 -1761.8,2553.48
PIN34: P6.10 U2.34 | length 426.6
  Top Layer w10: P6.10@-514.43,1800.14 -486.76,1800.14 -290.06,1603.44 U2.34@-290.06,1482.66
PIN38: P7.2 U2.38 | length 1034.8
  Top Layer w10: P7.2@-1268.9,1752.76 -1121.65,1752.76 v1(-868.11,1499.21) ; v1(-567.72,1420.08) -547.62,1399.98 U2.38@-392.42,1399.98
  Bottom Layer w10: P7.2@-1268.9,1752.76 P7.2@-1256.69,1752.76 ; v1(-868.11,1499.21) -707.87,1499.21 -628.74,1420.08 v1(-567.72,1420.08)
PIN42: P7.6 U2.42 | length 937.8
  Top Layer w11: P7.6@-1268.9,1352.76 -1179.15,1263 -604.71,1263 -546.47,1321.24 U2.42@-392.42,1321.24
PIN43: P7.7 U2.43 | length 905.2
  Top Layer w10: P7.7@-1268.9,1252.76 -1258.65,1242.5 -592.14,1242.5 -533.09,1301.56 U2.43@-392.42,1301.56
RXD0: P5.5 R9.1 U2.17 | length 1495.5
  Top Layer w10: U2.17@-49.9,1281.87 170.09,1281.87 355.12,1096.85 702.05,1096.85 P5.5@849.21,949.68 849.21,953.54 1149.21,1253.54 R9.1@1179.92,1253.54
RXD1: P6.1 R8.2 | length 471.9
  Top Layer w10: R8.2@7.09,1577.17 58.6,1577.17 229.07,1747.64 314.57,1747.64 367.07,1800.14 P6.1@385.57,1800.14 ; 7.87,1561.42 8.58,1560.71
SPIN: C19.2 P4.8 R42.2 R43.2 U2.8 | length 904.1
  Top Layer w10: U2.8@-191.63,1140.14 -191.63,1071.55 -152.2,1032.13 -125,1032.13 -83.62,990.75 -83.62,689.53 P4.8@-15.35,621.26 ; v1(74.41,521.65) 75.98,523.23 C19.2@105.12,523.23 106.69,531.62 106.65,531.57 R42.2@106.65,412.05
  Bottom Layer w10: P4.8@-15.35,621.26 -15.35,611.42 v1(74.41,521.65)
START1: C3.1 P6.9 R13.1 START1.2 U2.33 | length 2809.7
  Top Layer w10: U2.33@-270.37,1482.66 -270.37,1656.09 P6.9@-414.43,1800.14 -414.43,1831.24 -375.2,1870.47 580.32,1870.47 v1(629.92,1820.87) ; v1(800,1820.87) 919.21,1701.65 C3.1@1199.61,1701.65 R13.1@1265.04,1701.65 1265.04,1771.73 1361.02,1867.72 1361.02,2138.98 START1.2@1473.23,2251.18
  Bottom Layer w10: v1(629.92,1820.87) v1(800,1820.87)
STOP1: C2.2 P5.7 R7.2 STOP1.2 U2.19 | length 2010.8
  Top Layer w10: U2.19@-49.9,1321.25 187.42,1321.25 368.43,1140.24 839.76,1140.24 P5.7@849.21,1149.68 894.96,1149.68 1082.28,1337.01 1082.28,1479.92 1132.76,1530.39 1259.45,1530.39 1259.84,1530.79 1365.04,1530.79 1473.23,1638.98 STOP1.2@1473.23,1748.03 ; STOP1.2@1468.9,1748.03 STOP1.2@1482.28,1748.03
SWCLK: P14.2 U2.47 | length 1134.8
  Top Layer w10: P14.2@-1268.9,720.76 -1191.73,797.92 -1191.73,829.92 -1088.9,932.76 -672.36,932.76 -445.28,1159.84 -445.28,1213.78 -436.24,1222.82 U2.47@-392.42,1222.82
SWDIO: P14.3 U2.48 | length 1162.5
  Top Layer w10: P14.3@-1268.9,620.76 -1214.96,674.69 -1214.96,732.44 -1034.65,912.76 -664.08,912.76 -392.42,1184.42 U2.48@-392.42,1203.13
TXD0: P5.6 R12.2 U2.18 | length 1441.5
  Top Layer w10: U2.18@-49.9,1301.56 178.76,1301.56 362.6,1117.72 781.18,1117.72 P5.6@849.21,1049.68 1111.34,1311.81 R12.2@1178.74,1311.81
TXD1: P6.2 R11.1 | length 349.6
  Top Layer w10: R11.1@7.09,1628.35 81.5,1628.35 253.29,1800.14 P6.2@285.57,1800.14
ZB: R4.3 R42.1 ZB1.1 | length 2328.9
  Top Layer w20: R42.1@163.28,421.64 220.47,364.45 ZB1.1@220.47,308.66
  Bottom Layer w10: ZB1.1@220.47,308.66 331.89,197.24 1443.31,197.24 1966.93,720.87 1966.93,813.27 R4.3@1903.03,877.17
pads on no net: R4.4 R4.5 R4.6 START1.3 START1.4 STOP1.3 STOP1.4

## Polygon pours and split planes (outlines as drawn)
GND on Top Layer "Bottom Layer-No Net" (solid, remove dead copper, pour order 84): -2285.39,3127.48 -2442.48,3127.48 -2442.48,1681.02 -2444.05,1679.45 -2436.57,1671.97 -1934.21,1671.97 -1583.03,1671.97 -1571.61,1683.38 -1568.07,1686.93 -1568.07,2128.27 -1568.07,2209.37 -1581.46,2222.75 -1590.12,2231.42 -1789.72,2231.42 -1808.23,2231.42 -1859.41,2282.6 -1879.49,2302.68 -1879.49,2519.6 -1879.49,2548.34 -1896.02,2564.88 -2158.23,2827.08 -2158.23,3127.87
PGND on Top Layer "Bottom Layer-No Net" (solid, remove dead copper, pour order 51): 7.48,2509.06 261.02,2509.06 266.93,2509.06 271.26,2504.72 271.26,2440.94 271.26,2421.26 264.96,2414.96 262.2,2412.2 86.61,2412.2 42.91,2412.2 7.48,2447.64
PGND on Top Layer "Bottom Layer-No Net" (solid, remove dead copper, pour order 52): -1007.48,2508.66 -793.31,2508.66 -770.08,2508.66 -765.35,2503.94 -764.57,2503.15 -764.57,2417.72 -764.57,2409.45 -770.08,2403.94 -771.26,2402.76 -949.61,2402.76 -966.54,2402.76 -1007.48,2443.7
AX on Top Layer "Bottom Layer-No Net" (solid, remove dead copper, pour order 54): -1632.28,2739.37 -1632.28,2626.77 -1616.14,2610.63 -1214.57,2610.63 -1204.05,2621.14 -1204.05,2757.6 -1193.15,2768.5 -1190.16,2768.5 -951.57,2768.5 -951.18,2768.9 -951.18,3034.65 -951.18,3056.3 -959.45,3064.57 -1375.98,3064.57 -1428.74,3064.57 -1440.94,3052.36 -1474.41,3018.9 -1474.41,2817.72 -1474.41,2793.7 -1499.61,2768.5 -1508.27,2759.84 -1615.35,2759.84
AI on Top Layer "Bottom Layer-No Net" (solid, remove dead copper, pour order 56): -1032.24,2752.36 -1032.24,2627.17 -1024.76,2619.69 -1015.31,2610.24 -764.53,2610.24 -733.82,2610.24 -726.73,2617.32 -724.76,2619.29 -724.76,2718.9 -724.76,2742.91 -734.21,2752.36
BX on Top Layer "Bottom Layer-No Net" (solid, remove dead copper, pour order 59): -538.19,2744.49 -553.54,2744.49 -564.96,2733.07 -568.9,2729.13 -568.9,2628.35 -568.9,2617.72 -558.66,2607.48 -553.15,2601.97 -277.95,2601.97 -203.94,2601.97 -193.7,2612.2 -192.13,2613.78 -192.13,2740.94 -192.13,2764.96 -179.92,2777.17 -175.2,2781.89 -71.65,2781.89 50,2781.89 64.17,2796.06 72.44,2804.33 72.44,3022.83 72.44,3048.03 56.3,3064.17 54.33,3066.14 -236.22,3066.14 -372.44,3066.14 -382.68,3055.91 -404.72,3033.86 -404.72,2804.33 -404.72,2770.08 -430.71,2744.09
BI on Top Layer "Bottom Layer-No Net" (solid, remove dead copper, pour order 61): -36.61,2759.06 -48.82,2746.85 -48.82,2658.27 -48.82,2631.1 -38.98,2621.26 183.07,2621.26 278.74,2621.26 285.43,2627.95 291.34,2633.86 291.34,2759.06
CX on Top Layer "Bottom Layer-No Net" (solid, remove dead copper, pour order 66): 449.61,2766.93 440.94,2758.27 440.94,2677.56 440.94,2615.35 446.06,2610.24 448.82,2607.48 731.5,2607.48 819.69,2607.48 830.32,2618.11 841.73,2629.53 841.73,2700 841.73,2750.39 859.06,2767.72 868.5,2777.17 1093.31,2777.17 1109.06,2777.17 1117.72,2785.83 1118.11,2786.22 1118.11,3035.83 1118.11,3047.24 1104.33,3061.02 1100.39,3064.96 820.08,3064.96 632.28,3064.96 622.83,3055.51 609.84,3042.52 609.84,2873.23 609.84,2777.95 598.82,2766.93
CI on Top Layer "Bottom Layer-No Net" (solid, remove dead copper, pour order 69): 995.67,2750.39 995.67,2633.07 995.67,2625.98 1003.54,2618.11 1005.12,2616.54 1250,2616.54 1311.42,2616.54 1318.9,2624.02 1320.47,2625.59 1320.47,2725.2 1320.47,2728.74 1298.82,2750.39
+48V on Top Layer "Bottom Layer-No Net" (solid, remove dead copper, pour order 72): -2110.24,3368.11 -2133.07,3345.28 -2133.07,2953.54 -2133.07,2893.7 -2163.39,2863.39 -2164.17,2862.6 -2239.76,2862.6 -2246.85,2862.6 -2271.26,2838.19 -2275.2,2834.25 -2275.2,2759.45 -2275.2,2683.07 -2266.54,2674.41 -2212.2,2620.08 -1906.69,2620.08 -1841.73,2620.08 -1814.17,2647.64 -1814.17,2759.45 -1814.17,2763.78 -1798.82,2779.13 -1772.83,2805.12 -1553.15,2805.12 -1543.7,2805.12 -1530.71,2818.11 -1528.35,2820.47 -1528.35,3012.2 -1528.35,3015.35 -1479.53,3064.17 -1431.5,3112.2 -500.39,3112.2 1389.76,3112.2 1423.23,3078.74 1483.46,3018.5 1791.34,3018.5 1795.28,3018.5 1836.61,3059.84 1838.98,3062.2 1838.98,3423.23
+48V on Top Layer "Bottom Layer-No Net" (solid, remove dead copper, pour order 73): -2133.07,3344.78 -2133.07,3400.79 -2133.46,3401.18 -2070.47,3464.17 521.65,3464.17 1719.58,3464.17 1838.98,3344.78 1838.98,3237.4 -2085.83,3237.4 -2133.07,3284.65
+48V on Top Layer "Bottom Layer-No Net" (solid, remove dead copper, pour order 76): -790.16,3124.02 -755.51,3089.37 -755.51,2835.7 -755.51,2819.69 -738.98,2803.15 -736.61,2800.79 -451.97,2800.79 -443.7,2809.06 -443.7,3074.41 -387.8,3130.31 -411.42,3153.94 -774.02,3153.94
+48V on Top Layer "Bottom Layer-No Net" (solid, remove dead copper, pour order 75): 220.47,3117.32 255.12,3082.68 255.12,2829 255.12,2812.99 271.65,2796.46 274.02,2794.09 558.66,2794.09 566.93,2802.36 566.93,3067.72 622.83,3123.62 599.21,3147.24 236.61,3147.24
DM_IN on Top Layer "Bottom Layer-No Net" (solid, remove dead copper, pour order 78): -2343.31,1628.74 -2343.31,1409.48 -2335.43,1400.23 -2331.89,1396.06 -2095.28,1396.06 -2093.31,1396.06 -2090.94,1398.84 -2086.61,1403.93 -2086.61,1530.21 -2086.61,1610.24 -2102.36,1628.74
GND on Top Layer "Bottom Layer-No Net" (solid, remove dead copper, pour order 80): -1749.21,1528.74 -1749.21,1425.2 -1749.21,1386.22 -1740.55,1377.56 -1737.01,1374.02 -1550.79,1374.02 -1550.79,1553.94 -1553.94,1557.09 -1566.93,1570.08 -1749.21,1570.08
GND on Top Layer "Bottom Layer-No Net" (solid, remove dead copper, pour order 81): -1731.1,939.37 -1731.1,925.59 -1761.42,895.28 -1762.99,893.7 -1762.99,829.92 -1762.99,788.98 -1758.27,784.25 -1743.31,769.29 -1602.36,769.29 -1596.46,769.29 -1582.28,783.46 -1583.46,784.65 -1583.46,931.1 -1583.46,934.25 -1610.24,961.02 -1618.11,968.9 -1718.5,968.9
+15V on Top Layer "Bottom Layer-No Net" (solid, remove dead copper, pour order 82): -2067.72,1000.39 -2205.12,1000.39 -2219.68,985.83 -2219.68,874.02 -2219.68,671.26 -2214.17,665.75 -2207.87,659.45 -2009.45,659.45 -2009.45,977.17 -2030.31,998.03
GND on Top Layer "Bottom Layer-No Net" (solid, remove dead copper, pour order 86): 1349.71,1956.04 -1549.11,1956.04 -1597.93,2004.86 -1630.21,2037.15 -1630.21,2231.63 -1628.63,2231.63 -1603.44,2256.83 -1595.17,2265.1 -731.39,2265.1 1347.35,2265.1 1364.67,2247.78 1384.36,2228.09 1384.36,2017.85
PGND on Top Layer "Bottom Layer-No Net" (solid, remove dead copper, pour order 87): 1056.69,2522.44 1056.69,2412.2 1070.08,2398.82 1073.23,2395.67 1296.06,2395.67 1303.15,2395.67 1320.08,2412.6 1320.47,2412.99 1320.47,2522.83
PGND on Top Layer "Bottom Layer-No Net" (solid, remove dead copper, pour order 88): 1429.13,2775.2 1429.13,2608.66 1460.63,2577.17 1461.42,2577.95 1812.2,2577.95 1812.2,2754.72 1832.68,2775.2
PGND on Top Layer "Bottom Layer-No Net" (solid, remove dead copper, pour order 90): 1461.42,2577.95 1461.81,2578.35 2155.51,2578.35 2155.51,2943.31 2132.68,2966.14 2131.89,2965.35 1660.63,2965.35 1409.06,2965.35 1382.68,2938.98 1375.2,2931.5 1375.2,2627.17
PGND on Top Layer "Bottom Layer-No Net" (solid, remove dead copper, pour order 93): -1847.24,2566.93 -1847.24,2370.87 -1828.74,2352.36 -1828.35,2351.97 -1733.07,2351.97 -1702.76,2351.97 -1692.52,2362.2 -1690.94,2363.78 -1690.94,2519.68 -1690.94,2558.27 -1705.12,2572.44 -1708.66,2575.98 -1835.43,2575.98
GND on Top Layer "Bottom Layer-No Net" (solid, remove dead copper, pour order 65): -2411.47,909.12 -2409.9,907.54 -1294.54,907.54 -1204.39,907.54 -1180.37,931.56 -1177.62,934.32 -1177.62,1227.23 -1177.62,1818.57 -1144.15,1852.03 -1125.58,1870.6 73.96,1870.6 1384.65,1870.6 1414.12,1900.06 1426.72,1912.66 1426.72,2111.48 1426.72,2141.8 1459.79,2174.87 1465.3,2180.38 2040.1,2180.38 2086.95,2180.38 2117.27,2150.06 2124.35,2142.98 2124.35,803.21 2124.35,129.2 2117.27,122.11 2084.2,89.04 -2411.08,89.04
GND on Top Layer "Bottom Layer-No Net" (solid, remove dead copper, pour order 68): 1426.72,2141.8 1426.72,2472.78 1442.13,2488.19 1443.7,2489.76 1729.13,2489.76 2112.2,2489.76 2124.02,2477.95 2127.95,2474.02 2127.95,2155.12
NetCF1_1 on Top Layer "Bottom Layer-No Net" (solid, remove dead copper, pour order 71): -1835.04,1245.67 -1760.24,1245.67 -1755.91,1250 -1748.82,1257.09 -1748.82,1331.5 -1748.82,1348.82 -1762.6,1362.6 -1778.35,1378.35 -1778.35,1447.64 -1778.35,1518.9 -1788.98,1529.53 -1790.55,1531.1 -1918.9,1531.1 -2012.6,1531.1 -2035.83,1507.87 -2051.97,1491.73 -2051.97,1266.93 -2051.97,1266.14 -2040.16,1254.33 -2039.37,1255.12 -1981.1,1255.12 -1978.35,1255.12 -1975.59,1257.87 -1975.59,1328.74 -1975.59,1341.73 -1962.6,1354.72 -1835.04,1354.72
+5V on Top Layer "Bottom Layer-No Net" (solid, remove dead copper, pour order 74): -1798.82,557.48 -1800,556.3 -1800,401.97 -1800,288.58 -1790.94,279.53 -1789.37,277.95 -1651.97,277.95 -1541.73,277.95 -1538.58,281.1 -1539.37,281.89 -1539.37,414.57 -1539.37,596.46 -1545.67,602.76 -1549.21,606.3 -1656.69,606.3 -1719.68,606.3 -1721.65,604.33
GND on Bottom Layer "Bottom Layer-No Net" (solid, remove dead copper, pour order 94): -1597.24,2265.35 -1846.06,2265.35 -1864.57,2265.35 -1881.1,2248.82 -1892.91,2237.01 -1892.91,2064.96 -1846.85,2064.96 -1687.8,1905.91 -1681.5,1899.61 -1574.02,1899.61 -1574.02,1991.34 -1568.11,1997.24
AX on Bottom Layer "Bottom Layer-No Net" (solid, remove dead copper, pour order 53): -1634.02,2739.37 -1634.02,2626.77 -1617.87,2610.63 -1216.3,2610.63 -1205.79,2621.14 -1205.79,2757.6 -1194.88,2768.5 -1191.89,2768.5 -953.31,2768.5 -952.91,2768.9 -952.91,3034.65 -952.91,3056.3 -961.18,3064.57 -1377.72,3064.57 -1430.47,3064.57 -1442.68,3052.36 -1476.14,3018.9 -1476.14,2817.72 -1476.14,2793.7 -1501.34,2768.5 -1510,2759.84 -1617.09,2759.84
AI on Bottom Layer "Bottom Layer-No Net" (solid, remove dead copper, pour order 55): -1032.28,2752.36 -1032.28,2627.17 -1024.8,2619.69 -1015.35,2610.24 -764.57,2610.24 -733.86,2610.24 -726.77,2617.32 -724.8,2619.29 -724.8,2718.9 -724.8,2742.91 -734.25,2752.36
AX on Bottom Layer "Bottom Layer-No Net" (solid, remove dead copper, pour order 57): -1216.3,2610.63 -1215.91,2610.24 -1091.73,2610.24 -1063.39,2610.24 -1056.3,2617.32 -1053.54,2620.08 -1053.54,2768.5 -1053.54,2791.34 -1073.23,2811.02 -1237.01,2811.02
BX on Bottom Layer "Bottom Layer-No Net" (solid, remove dead copper, pour order 58): -537.8,2744.88 -553.15,2744.88 -564.57,2733.46 -568.5,2729.53 -568.5,2628.74 -568.5,2618.11 -558.27,2607.87 -552.76,2602.36 -277.56,2602.36 -203.54,2602.36 -193.31,2612.6 -191.73,2614.17 -191.73,2741.34 -191.73,2765.35 -179.53,2777.56 -174.8,2782.28 -71.26,2782.28 50.39,2782.28 64.57,2796.46 72.83,2804.72 72.83,3023.23 72.83,3048.43 56.69,3064.57 54.72,3066.54 -235.83,3066.54 -372.05,3066.54 -382.28,3056.3 -404.33,3034.25 -404.33,2804.72 -404.33,2770.47 -430.31,2744.49
BI on Bottom Layer "Bottom Layer-No Net" (solid, remove dead copper, pour order 60): -37.36,2758.66 -49.57,2746.46 -49.57,2657.87 -49.57,2630.71 -39.72,2620.87 182.32,2620.87 277.99,2620.87 284.69,2627.56 290.59,2633.46 290.59,2758.66
BX on Bottom Layer "Bottom Layer-No Net" (solid, remove dead copper, pour order 62): -203.54,2602.36 -75.2,2602.36 -67.32,2610.24 -64.57,2612.99 -64.57,2798.03 -194.49,2798.03 -200.79,2791.73
CX on Bottom Layer "Bottom Layer-No Net" (solid, remove dead copper, pour order 64): 450,2767.72 441.34,2759.06 441.34,2678.35 441.34,2616.14 446.46,2611.02 449.21,2608.27 731.89,2608.27 820.08,2608.27 830.71,2618.9 842.13,2630.31 842.13,2700.79 842.13,2751.18 859.45,2768.5 868.9,2777.95 1093.7,2777.95 1109.45,2777.95 1118.11,2786.61 1118.5,2787.01 1118.5,3036.61 1118.5,3048.03 1104.72,3061.81 1100.79,3065.75 820.47,3065.75 632.68,3065.75 623.23,3056.3 610.24,3043.31 610.24,2874.02 610.24,2778.74 599.21,2767.72
CI on Bottom Layer "Bottom Layer-No Net" (solid, remove dead copper, pour order 67): 995.28,2750 995.28,2632.68 995.28,2625.59 1003.15,2617.72 1004.72,2616.14 1249.61,2616.14 1311.02,2616.14 1318.5,2623.62 1320.08,2625.2 1320.08,2724.8 1320.08,2728.35 1298.43,2750
DM_IN on Bottom Layer "Bottom Layer-No Net" (solid, remove dead copper, pour order 77): -2342.52,1628.54 -2342.52,1441.93 -2334.65,1434.06 -2331.1,1430.51 -2094.49,1430.51 -2092.52,1430.51 -2090.16,1432.87 -2085.83,1437.2 -2085.83,1544.69 -2085.83,1612.8 -2101.57,1628.54
PGND on Bottom Layer "Bottom Layer-No Net" (solid, remove dead copper, pour order 79): -1854.33,2497.1 -1854.33,2423.78 -1854.33,2362.38 -1811.81,2322.18 -1778.35,2290.55 -1041.73,2290.55 1342.91,2290.55 1359.06,2305.81 1378.74,2324.42 1378.74,2445.37 1378.74,2528.73 1363.78,2542.87 1342.91,2562.6 -1725.98,2562.6
GND on Bottom Layer "Bottom Layer-No Net" (solid, remove dead copper, pour order 83): -2291.14,3126.97 -2448.23,3126.97 -2448.23,1680.51 -2449.8,1678.94 -2442.32,1671.46 -1939.96,1671.46 -1588.78,1671.46 -1577.36,1682.87 -1573.82,1686.42 -1573.82,2127.76 -1573.82,2208.86 -1587.2,2222.24 -1595.87,2230.91 -1795.47,2230.91 -1813.98,2230.91 -1865.16,2282.09 -1885.24,2302.17 -1885.24,2519.09 -1885.24,2547.83 -1901.77,2564.37 -2163.98,2826.57 -2163.98,3127.36
+48V on Bottom Layer "Bottom Layer-No Net" (solid, remove dead copper, pour order 70): -2111.02,3368.9 -2133.86,3346.06 -2133.86,2954.33 -2133.86,2894.49 -2164.17,2864.17 -2164.96,2863.39 -2240.55,2863.39 -2247.64,2863.39 -2272.05,2838.98 -2275.98,2835.04 -2275.98,2760.24 -2275.98,2683.86 -2267.32,2675.2 -2212.99,2620.87 -1907.48,2620.87 -1842.52,2620.87 -1814.96,2648.43 -1814.96,2760.24 -1814.96,2764.57 -1799.61,2779.92 -1773.62,2805.91 -1553.94,2805.91 -1544.49,2805.91 -1531.5,2818.9 -1529.13,2821.26 -1529.13,3012.99 -1529.13,3016.14 -1480.31,3064.96 -1432.28,3112.99 -501.18,3112.99 1388.98,3112.99 1422.44,3079.53 1482.68,3019.29 1790.55,3019.29 1794.49,3019.29 1835.83,3060.63 1838.19,3062.99 1838.19,3424.02
GND on Bottom Layer "Bottom Layer-No Net" (solid, remove dead copper, pour order 85): 1347.64,1956.3 -1551.18,1956.3 -1600,2005.12 -1632.28,2037.4 -1632.28,2231.89 -1630.71,2231.89 -1605.51,2257.09 -1597.24,2265.35 -733.46,2265.35 1345.28,2265.35 1362.6,2248.03 1382.28,2228.35 1382.28,2018.11
PGND on Bottom Layer "Bottom Layer-No Net" (solid, remove dead copper, pour order 89): 1342.91,2290.55 2135.43,2290.55 2135.43,2965.23 2140.55,2970.08 2136.22,2965.98 1802.36,2965.98 1410.63,2965.98 1361.02,2919.01 1359.45,2917.52 1359.45,2610.75 1359.45,2359.14 1342.91,2343.48
+48V on Bottom Layer "Bottom Layer-No Net" (solid, remove dead copper, pour order 91): -805.91,3115.35 -781.5,3115.35 -757.09,3090.94 -755.51,3089.37 -755.51,3067.72 -755.51,2836.5 -719.8,2800.79 -719.02,2800 -451.97,2800 -442.91,2809.06 -442.52,2809.45 -442.52,3056.69 -442.52,3075.2 -392.13,3125.59 -442.13,3175.59 -775.59,3175.59
+48V on Bottom Layer "Bottom Layer-No Net" (solid, remove dead copper, pour order 92): 183.46,3127.56 210.24,3127.56 255.12,3082.68 255.12,2827.95 255.12,2818.5 278.74,2794.88 279.92,2793.7 408.66,2793.7 557.87,2793.7 566.93,2802.76 566.93,2959.84 566.93,3067.72 632.28,3133.07 605.12,3160.24 446.06,3160.24
GND on Bottom Layer "Bottom Layer-No Net" (solid, remove dead copper, pour order 63): -2400.39,909.84 -2398.82,908.27 -1283.46,908.27 -1193.31,908.27 -1169.29,932.28 -1166.54,935.04 -1166.54,1227.95 -1166.54,1819.29 -1133.07,1852.76 -1114.5,1871.32 85.04,1871.32 1395.73,1871.32 1425.2,1900.79 1437.8,1913.39 1437.8,2112.2 1437.8,2142.52 1470.87,2175.59 1476.38,2181.1 2051.18,2181.1 2098.03,2181.1 2128.35,2150.79 2135.43,2143.7 2135.43,803.94 2135.43,129.92 2128.35,122.83 2095.28,89.76 -2400,89.76
PGND on Bottom Solder "Bottom Layer-No Net" (solid): 1718.11,3183.07 1718.11,3042.13 1704.72,3028.74 1704.33,3028.35 1502.76,3028.35 1498.03,3028.35 1375.2,3151.18 1357.87,3168.5 1357.87,3252.36
PGND on Bottom Solder "Bottom Layer-No Net" (solid, pour order 48): -1788.19,2570.87 -1831.1,2527.95 -1831.1,2371.26 -1831.1,2351.97 -1798.03,2318.9 -1788.98,2309.84 -1618.9,2309.84 -989.37,2309.84 -904.72,2394.49 -901.18,2398.03 -805.12,2398.03 -805.12,2388.58 -730.31,2313.78 -729.53,2312.99 18.9,2312.99 33.07,2312.99 122.44,2402.36 125.2,2405.12 206.69,2405.12 214.57,2405.12 238.19,2381.5 294.88,2324.8 1003.94,2324.8 1096.85,2324.8 1159.06,2387.01 1162.2,2390.16 1240.16,2390.16 1240.16,2388.98 1303.54,2325.59 2049.61,2325.59 2049.61,2883.07 2001.18,2931.5 1989.76,2942.91 1501.97,2942.91 1418.5,2942.91 1387.8,2912.2 1379.53,2903.94 1379.53,2616.93 1379.53,2614.96 1322.44,2557.87 1309.84,2570.47 -1747.24,2570.47
+48V on Bottom Solder "Bottom Layer-No Net" (solid): -2109.45,3332.68 -2109.45,2955.91 -2109.45,2871.26 -2130.71,2850 -2148.43,2832.28 -2187.4,2832.28 -2207.87,2832.28 -2225.98,2814.17 -2231.1,2809.06 -2231.1,2735.43 -2231.1,2695.67 -2217.72,2682.28 -2185.43,2650 -2078.74,2650 -1870.08,2650 -1850,2670.08 -1842.13,2677.95 -1842.13,2742.52 -1842.13,2788.19 -1811.42,2818.9 -1794.49,2835.83 -1584.65,2835.83 -1557.87,2835.83 -1544.49,2849.21 -1544.49,3011.42 -1544.49,3040.16 -1455.51,3129.13 -1442.52,3142.13 -783.46,3142.13 -775.59,3142.13 -738.98,3105.51 -737.8,3104.33 -737.8,2910.63 -737.8,2890.94 -673.23,2826.38 -474.8,2826.38 -469.29,2826.38 -456.3,2839.37 -456.3,3062.2 -456.3,3088.98 -422.05,3123.23 -407.87,3137.4 245.67,3137.4 245.67,3134.65 281.89,3098.43 279.53,3096.06 279.53,2870.87 279.53,2867.32 333.46,2813.39 338.19,2818.11 537.8,2818.11 537.8,3071.65 602.36,3136.22 620.87,3154.72 1590.16,3154.72 1689.76,3154.72 1711.02,3175.98 1718.11,3183.07 1718.11,3349.61 -2099.21,3349.61 -2109.45,3339.37
CX on Bottom Solder "Bottom Layer-No Net" (solid): 641.34,3048.43 624.02,3031.1 624.02,2942.13 624.02,2777.56 601.57,2755.12 601.18,2754.72 512.2,2754.72 459.06,2754.72 451.57,2747.24 448.82,2744.49 448.82,2651.18 448.82,2626.77 457.48,2618.11 459.06,2616.54 793.31,2616.54 814.96,2616.54 826.77,2628.35 831.1,2632.68 831.1,2744.09 831.1,2760.24 858.27,2787.4 861.02,2790.16 1096.46,2790.16 1101.18,2790.16 1107.87,2796.85 1108.66,2797.64 1108.66,2918.9 1108.66,3033.46 1093.31,3048.82
BX on Bottom Solder "Bottom Layer-No Net" (solid): -372.83,3051.97 -390.94,3033.86 -390.94,3008.66 -390.94,2765.35 -421.65,2734.65 -424.02,2732.28 -525.98,2732.28 -542.52,2732.28 -554.72,2720.08 -557.48,2717.32 -557.48,2623.23 -557.48,2620.87 -549.21,2612.6 -548.82,2612.2 -227.17,2612.2 -216.14,2612.2 -207.48,2620.87 -203.94,2624.41 -203.94,2751.18 -203.94,2770.47 -180.31,2794.09 -179.13,2795.28 25.98,2795.28 44.49,2795.28 60.63,2811.42 62.2,2812.99 62.2,3032.28 62.2,3041.34 51.57,3051.97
